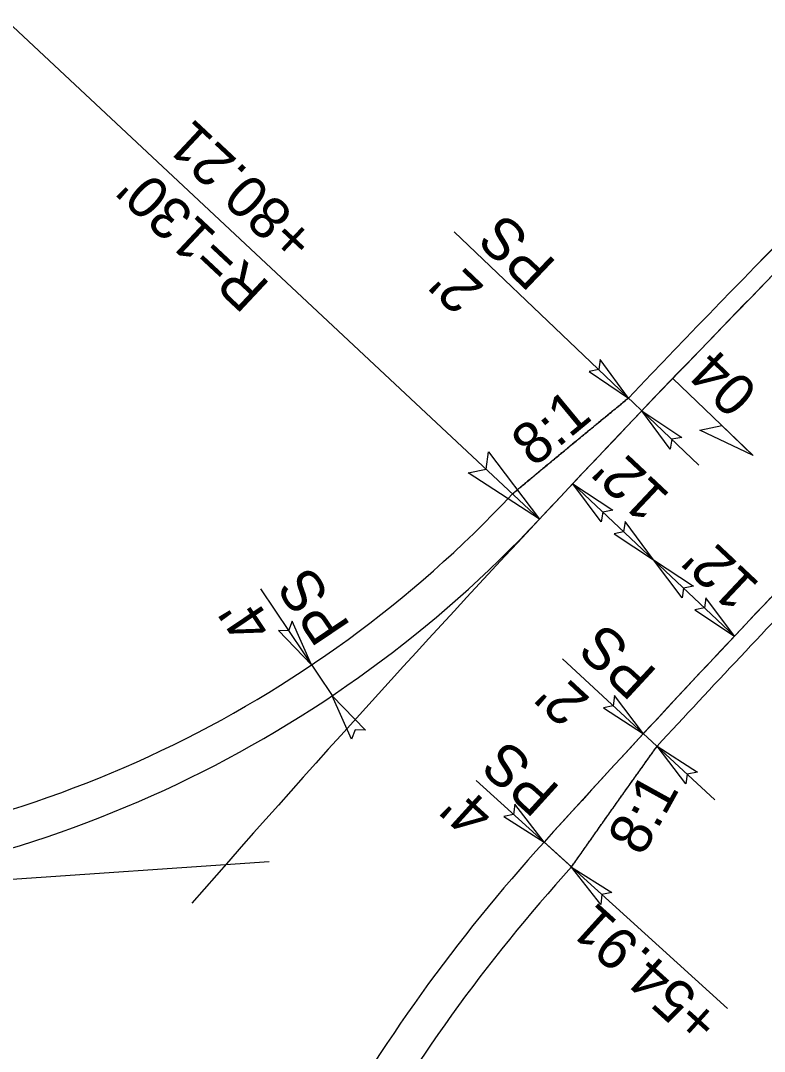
# Model space of a CAD drawing. Extents: x 1183930 to 1185370, y 573068 to 574871.
# Drawn here: x 1184757.1 to 1184837.4, y 574383.3 to 574494.7 of the extents above; entities that cross this region are included whole.
import ezdxf

# ---------------------------------------------------------------- set-up
doc = ezdxf.new("R2010")
doc.units = 0
for name, color, linetype in [('E_NCDOT_Terrain_Model_Contour_Minor', 7, 'Continuous'), ('E_NCDOT_Vertical_Profile_Ground_Line', 7, 'Continuous'), ('P_NCDOT_Horizontal_Alignment', 7, 'Continuous'), ('PC_COLUMN', 7, 'Continuous'), ('PC_OBJECT', 7, 'Continuous'), ('PC_PADFOOTING', 7, 'Continuous'), ('PC_SLAB', 7, 'Continuous')]:
    doc.layers.add(name, color=color, linetype=linetype)

msp = doc.modelspace()

# ---------------------------------------------------------------- linework, layer by layer
for points in [[(1184818.48, 574456.78), (1184822.74, 574453.91), (1184819.68, 574458.08), (1184819.53, 574456.98)], [(1184827.25, 574448.41), (1184824.19, 574452.53), (1184828.5, 574449.67), (1184827.41, 574449.47)], [(1184819.81, 574440.55), (1184816.72, 574444.65), (1184821.04, 574441.82), (1184819.96, 574441.6)], [(1184821.18, 574439.26), (1184825.46, 574436.43), (1184822.37, 574440.57), (1184822.22, 574439.47)], [(1184828.55, 574432.32), (1184825.46, 574436.43), (1184829.78, 574433.59), (1184828.7, 574433.38)], [(1184829.91, 574431.04), (1184834.2, 574428.2), (1184831.11, 574432.35), (1184830.96, 574431.25)], [(1184784.96, 574428.79), (1184788.51, 574425.08), (1184786.42, 574429.81), (1184786.03, 574428.77)], [(1184792.85, 574417.07), (1184790.74, 574421.76), (1184794.33, 574418.04), (1184793.22, 574418.07)], [(1184820.05, 574420.46), (1184824.36, 574417.66), (1184821.24, 574421.78), (1184821.1, 574420.68)], [(1184828.95, 574412.23), (1184825.83, 574416.3), (1184830.18, 574413.51), (1184829.09, 574413.29)], [(1184809.29, 574408.71), (1184813.63, 574405.95), (1184810.46, 574410.04), (1184810.34, 574408.94)], [(1184819.75, 574399.22), (1184816.59, 574403.26), (1184820.96, 574400.51), (1184819.88, 574400.28)]]:
    msp.add_lwpolyline(points, close=True)
at = {"layer": 'E_NCDOT_Terrain_Model_Contour_Minor'}
msp.add_line((1184718.19, 574529.63), (1184813.13, 574440.82), dxfattribs=at)
msp.add_lwpolyline([(1184807.61, 574448.1), (1184813.13, 574440.82), (1184805.42, 574445.83), (1184807.36, 574446.22)], close=True, dxfattribs=at)
at = {"layer": 'E_NCDOT_Vertical_Profile_Ground_Line'}
for centre, radius, start, end in [((1186063.32, 573271.23), 1714, 134.45507, 136.36856), ((1186063.32, 573271.23), 1714, 134.45507, 136.36856), ((1184718.19, 574529.63), 126, 273.9365, 316.9078), ((1184718.19, 574529.63), 126, 273.9365, 316.9078), ((1186063.32, 573271.23), 1686, 136.32379, 137.22125), ((1186063.32, 573271.23), 1686, 136.32379, 137.22125), ((1184950.59, 574281.59), 181, 137.7604, 163.7957), ((1184950.59, 574281.59), 181, 137.7604, 163.7957)]:
    msp.add_arc(centre, radius, start, end, dxfattribs=at)
for points in [[(1184810.21, 574443.55), (1184810.41, 574443.73), (1184810.83, 574444.07), (1184811.46, 574444.59), (1184812.08, 574445.12), (1184812.71, 574445.64), (1184813.33, 574446.16), (1184813.96, 574446.68), (1184814.58, 574447.19), (1184815.21, 574447.71), (1184815.84, 574448.23), (1184816.46, 574448.75), (1184817.09, 574449.27), (1184817.72, 574449.79), (1184818.34, 574450.3), (1184818.97, 574450.82), (1184819.6, 574451.34), (1184820.23, 574451.85), (1184820.86, 574452.37), (1184821.48, 574452.88), (1184822.11, 574453.4), (1184822.53, 574453.74), (1184822.74, 574453.91)], [(1184810.21, 574443.55), (1184810.41, 574443.73), (1184810.83, 574444.07), (1184811.46, 574444.59), (1184812.08, 574445.12), (1184812.71, 574445.64), (1184813.33, 574446.16), (1184813.96, 574446.68), (1184814.58, 574447.19), (1184815.21, 574447.71), (1184815.84, 574448.23), (1184816.46, 574448.75), (1184817.09, 574449.27), (1184817.72, 574449.79), (1184818.34, 574450.3), (1184818.97, 574450.82), (1184819.6, 574451.34), (1184820.23, 574451.85), (1184820.86, 574452.37), (1184821.48, 574452.88), (1184822.11, 574453.4), (1184822.53, 574453.74), (1184822.74, 574453.91)], [(1184816.59, 574403.26), (1184816.74, 574403.48), (1184817.05, 574403.92), (1184817.51, 574404.57), (1184817.97, 574405.22), (1184818.43, 574405.88), (1184818.89, 574406.53), (1184819.35, 574407.18), (1184819.81, 574407.84), (1184820.27, 574408.49), (1184820.73, 574409.14), (1184821.19, 574409.79), (1184821.66, 574410.45), (1184822.12, 574411.1), (1184822.58, 574411.75), (1184823.04, 574412.4), (1184823.51, 574413.05), (1184823.97, 574413.7), (1184824.44, 574414.35), (1184824.9, 574415), (1184825.37, 574415.65), (1184825.68, 574416.09), (1184825.83, 574416.3)], [(1184816.59, 574403.26), (1184816.74, 574403.48), (1184817.05, 574403.92), (1184817.51, 574404.57), (1184817.97, 574405.22), (1184818.43, 574405.88), (1184818.89, 574406.53), (1184819.35, 574407.18), (1184819.81, 574407.84), (1184820.27, 574408.49), (1184820.73, 574409.14), (1184821.19, 574409.79), (1184821.66, 574410.45), (1184822.12, 574411.1), (1184822.58, 574411.75), (1184823.04, 574412.4), (1184823.51, 574413.05), (1184823.97, 574413.7), (1184824.44, 574414.35), (1184824.9, 574415), (1184825.37, 574415.65), (1184825.68, 574416.09), (1184825.83, 574416.3)]]:
    msp.add_open_spline(points, degree=3, dxfattribs=at)
at = {"layer": 'P_NCDOT_Horizontal_Alignment'}
msp.add_line((1184592.27, 574390.66), (1184783.93, 574403.85), dxfattribs=at)
for centre, radius, start, end in [((1186063.32, 573271.23), 1712, 134.45454, 138.77988), ((1186063.32, 573271.23), 1712, 134.45454, 136.90785), ((1186063.32, 573271.23), 1712, 134.45454, 136.90785), ((1186063.32, 573271.23), 1688, 134.45454, 137.76045), ((1186063.32, 573271.23), 1688, 134.45454, 137.76045), ((1184718.19, 574529.63), 130, 273.9365, 316.9078), ((1184718.19, 574529.63), 130, 273.9365, 316.9078), ((1184950.59, 574281.59), 185, 137.7604, 163.7957)]:
    msp.add_arc(centre, radius, start, end, dxfattribs=at)
at = {"layer": 'PC_COLUMN'}
msp.add_lwpolyline([(1184836.15, 574447.73), (1184830.44, 574450.45), (1184832.82, 574450.94)], close=True, dxfattribs=at)
at = {"layer": 'PC_OBJECT'}
msp.add_lwpolyline([(1184810.21, 574443.55), (1184810.21, 574443.55)], dxfattribs=at)
for centre, radius, start, end in [((1186063.32, 573271.23), 1714, 134.45454, 136.36856), ((1186063.32, 573271.23), 1712, 134.45454, 136.90785), ((1184718.19, 574529.63), 126, 273.9365, 316.9078), ((1184718.19, 574529.63), 130, 273.9365, 316.9078), ((1186063.32, 573271.23), 1686, 136.32379, 137.22125), ((1186063.32, 573271.23), 1688, 136.53929, 137.76045), ((1184950.59, 574281.59), 185, 137.7604, 163.7957), ((1184950.59, 574281.59), 181, 137.7604, 163.7957)]:
    msp.add_arc(centre, radius, start, end, dxfattribs=at)
for points in [[(1184822.74, 574453.91), (1184822.4, 574453.64), (1184822.23, 574453.5), (1184822.06, 574453.36), (1184821.89, 574453.22), (1184821.72, 574453.08), (1184821.55, 574452.94), (1184821.38, 574452.8), (1184821.21, 574452.66), (1184821.04, 574452.52), (1184820.87, 574452.38), (1184820.7, 574452.24), (1184820.53, 574452.1), (1184820.36, 574451.96), (1184820.19, 574451.82), (1184820.02, 574451.69), (1184819.85, 574451.55), (1184819.69, 574451.41), (1184819.52, 574451.27), (1184819.35, 574451.13), (1184819.18, 574450.99), (1184819.01, 574450.85), (1184818.84, 574450.71), (1184818.67, 574450.57), (1184818.55, 574450.47)], [(1184818.55, 574450.47), (1184818.5, 574450.43), (1184818.33, 574450.29), (1184818.16, 574450.15), (1184817.99, 574450.01), (1184817.82, 574449.87), (1184817.65, 574449.73), (1184817.48, 574449.59), (1184817.31, 574449.45), (1184817.14, 574449.31), (1184816.97, 574449.17), (1184816.8, 574449.03), (1184816.63, 574448.89), (1184816.46, 574448.75), (1184816.29, 574448.61), (1184816.12, 574448.47), (1184815.96, 574448.33), (1184815.79, 574448.19), (1184815.62, 574448.05), (1184815.45, 574447.91), (1184815.28, 574447.77), (1184815.11, 574447.63), (1184814.94, 574447.49), (1184814.77, 574447.35), (1184814.6, 574447.21), (1184814.43, 574447.07), (1184814.37, 574447.02)], [(1184814.37, 574447.02), (1184814.26, 574446.93), (1184814.09, 574446.79), (1184813.92, 574446.65), (1184813.75, 574446.51), (1184813.59, 574446.37), (1184813.42, 574446.23), (1184813.25, 574446.09), (1184813.08, 574445.94), (1184812.91, 574445.8), (1184812.74, 574445.66), (1184812.57, 574445.52), (1184812.4, 574445.38), (1184812.23, 574445.24), (1184812.06, 574445.1), (1184811.89, 574444.96), (1184811.73, 574444.82), (1184811.56, 574444.68), (1184811.39, 574444.54), (1184811.22, 574444.4), (1184811.05, 574444.26), (1184810.88, 574444.12), (1184810.71, 574443.98), (1184810.54, 574443.83), (1184810.37, 574443.69), (1184810.21, 574443.55)]]:
    msp.add_spline(points, degree=3, dxfattribs=at)
for points in [[(1184825.67, 574416.08), (1184825.72, 574416.15), (1184825.78, 574416.23), (1184825.83, 574416.3)], [(1184824.9, 574415), (1184824.92, 574415.03), (1184824.93, 574415.05), (1184824.95, 574415.07)], [(1184824.95, 574415.07), (1184824.95, 574415.08), (1184824.96, 574415.09), (1184824.97, 574415.1)], [(1184824.97, 574415.1), (1184824.99, 574415.13), (1184825.02, 574415.17), (1184825.04, 574415.2)], [(1184825.04, 574415.2), (1184825.07, 574415.24), (1184825.1, 574415.29), (1184825.13, 574415.33)], [(1184825.13, 574415.33), (1184825.17, 574415.38), (1184825.21, 574415.44), (1184825.25, 574415.49)], [(1184825.25, 574415.49), (1184825.26, 574415.5), (1184825.26, 574415.51), (1184825.27, 574415.52)], [(1184825.27, 574415.52), (1184825.3, 574415.57), (1184825.33, 574415.61), (1184825.37, 574415.65)], [(1184825.37, 574415.65), (1184825.37, 574415.67), (1184825.38, 574415.68), (1184825.39, 574415.69)], [(1184825.39, 574415.69), (1184825.4, 574415.7), (1184825.4, 574415.71), (1184825.41, 574415.72)], [(1184825.41, 574415.72), (1184825.45, 574415.77), (1184825.49, 574415.83), (1184825.53, 574415.88)], [(1184825.53, 574415.88), (1184825.54, 574415.9), (1184825.56, 574415.93), (1184825.57, 574415.95)], [(1184825.57, 574415.95), (1184825.58, 574415.96), (1184825.59, 574415.97), (1184825.6, 574415.98)], [(1184825.6, 574415.98), (1184825.61, 574415.99), (1184825.61, 574416), (1184825.62, 574416.01)], [(1184825.62, 574416.01), (1184825.63, 574416.02), (1184825.64, 574416.03), (1184825.64, 574416.04)], [(1184825.64, 574416.04), (1184825.65, 574416.06), (1184825.66, 574416.07), (1184825.67, 574416.08)], [(1184824.09, 574413.87), (1184824.1, 574413.89), (1184824.12, 574413.91), (1184824.13, 574413.93)], [(1184824.13, 574413.93), (1184824.15, 574413.95), (1184824.17, 574413.97), (1184824.18, 574414)], [(1184824.18, 574414), (1184824.2, 574414.03), (1184824.23, 574414.06), (1184824.25, 574414.09)], [(1184824.25, 574414.09), (1184824.26, 574414.1), (1184824.27, 574414.11), (1184824.27, 574414.13)], [(1184824.27, 574414.13), (1184824.29, 574414.15), (1184824.3, 574414.17), (1184824.32, 574414.19)], [(1184824.32, 574414.19), (1184824.34, 574414.22), (1184824.37, 574414.26), (1184824.39, 574414.29)], [(1184824.39, 574414.29), (1184824.41, 574414.31), (1184824.42, 574414.33), (1184824.44, 574414.35)], [(1184824.44, 574414.35), (1184824.47, 574414.4), (1184824.5, 574414.44), (1184824.53, 574414.48)], [(1184824.53, 574414.48), (1184824.54, 574414.49), (1184824.54, 574414.51), (1184824.55, 574414.52)], [(1184824.55, 574414.52), (1184824.57, 574414.54), (1184824.58, 574414.56), (1184824.6, 574414.58)], [(1184824.6, 574414.58), (1184824.63, 574414.62), (1184824.66, 574414.67), (1184824.69, 574414.71)], [(1184824.69, 574414.71), (1184824.72, 574414.75), (1184824.75, 574414.8), (1184824.78, 574414.84)], [(1184824.78, 574414.84), (1184824.82, 574414.9), (1184824.86, 574414.95), (1184824.9, 574415)], [(1184823.25, 574412.69), (1184823.29, 574412.75), (1184823.33, 574412.8), (1184823.37, 574412.86)], [(1184823.37, 574412.86), (1184823.39, 574412.89), (1184823.42, 574412.92), (1184823.44, 574412.95)], [(1184823.44, 574412.95), (1184823.46, 574412.99), (1184823.48, 574413.02), (1184823.51, 574413.05)], [(1184823.51, 574413.05), (1184823.55, 574413.12), (1184823.6, 574413.18), (1184823.65, 574413.25)], [(1184823.65, 574413.25), (1184823.65, 574413.26), (1184823.66, 574413.27), (1184823.67, 574413.28)], [(1184823.67, 574413.28), (1184823.74, 574413.38), (1184823.81, 574413.47), (1184823.88, 574413.57)], [(1184823.88, 574413.57), (1184823.89, 574413.59), (1184823.91, 574413.62), (1184823.93, 574413.64)], [(1184823.93, 574413.64), (1184823.94, 574413.66), (1184823.96, 574413.68), (1184823.97, 574413.7)], [(1184823.97, 574413.7), (1184824, 574413.75), (1184824.03, 574413.79), (1184824.06, 574413.83)], [(1184824.06, 574413.83), (1184824.07, 574413.84), (1184824.08, 574413.85), (1184824.09, 574413.87)], [(1184822.53, 574411.68), (1184822.55, 574411.71), (1184822.57, 574411.73), (1184822.58, 574411.75)], [(1184822.58, 574411.75), (1184822.59, 574411.76), (1184822.6, 574411.77), (1184822.6, 574411.78)], [(1184822.6, 574411.78), (1184822.64, 574411.82), (1184822.67, 574411.87), (1184822.7, 574411.91)], [(1184822.7, 574411.91), (1184822.7, 574411.92), (1184822.71, 574411.93), (1184822.72, 574411.94)], [(1184822.72, 574411.94), (1184822.74, 574411.97), (1184822.75, 574411.99), (1184822.77, 574412.01)], [(1184822.77, 574412.01), (1184822.77, 574412.02), (1184822.78, 574412.03), (1184822.79, 574412.04)], [(1184822.79, 574412.04), (1184822.8, 574412.05), (1184822.81, 574412.06), (1184822.81, 574412.07)], [(1184822.81, 574412.07), (1184822.83, 574412.1), (1184822.84, 574412.12), (1184822.86, 574412.14)], [(1184822.86, 574412.14), (1184822.87, 574412.15), (1184822.87, 574412.16), (1184822.88, 574412.17)], [(1184822.88, 574412.17), (1184822.92, 574412.23), (1184822.96, 574412.28), (1184823, 574412.34)], [(1184823, 574412.34), (1184823.01, 574412.36), (1184823.03, 574412.38), (1184823.04, 574412.4)], [(1184823.04, 574412.4), (1184823.05, 574412.41), (1184823.06, 574412.42), (1184823.07, 574412.43)], [(1184823.07, 574412.43), (1184823.1, 574412.48), (1184823.13, 574412.52), (1184823.16, 574412.56)], [(1184823.16, 574412.56), (1184823.19, 574412.61), (1184823.22, 574412.65), (1184823.25, 574412.69)], [(1184821.66, 574410.45), (1184821.73, 574410.54), (1184821.79, 574410.64), (1184821.86, 574410.74)], [(1184821.86, 574410.74), (1184821.88, 574410.76), (1184821.89, 574410.78), (1184821.91, 574410.8)], [(1184821.91, 574410.8), (1184821.94, 574410.85), (1184821.97, 574410.89), (1184822, 574410.93)], [(1184822, 574410.93), (1184822.04, 574410.99), (1184822.08, 574411.04), (1184822.12, 574411.1)], [(1184822.12, 574411.1), (1184822.13, 574411.11), (1184822.13, 574411.12), (1184822.14, 574411.13)], [(1184822.14, 574411.13), (1184822.18, 574411.18), (1184822.22, 574411.24), (1184822.26, 574411.29)], [(1184822.26, 574411.29), (1184822.33, 574411.4), (1184822.41, 574411.51), (1184822.49, 574411.62)], [(1184822.49, 574411.62), (1184822.5, 574411.63), (1184822.5, 574411.64), (1184822.51, 574411.65)], [(1184822.51, 574411.65), (1184822.52, 574411.66), (1184822.53, 574411.67), (1184822.53, 574411.68)], [(1184820.92, 574409.4), (1184820.95, 574409.46), (1184820.99, 574409.51), (1184821.03, 574409.57)], [(1184821.03, 574409.57), (1184821.09, 574409.64), (1184821.14, 574409.72), (1184821.19, 574409.79)], [(1184821.19, 574409.79), (1184821.21, 574409.82), (1184821.22, 574409.84), (1184821.24, 574409.86)], [(1184821.24, 574409.86), (1184821.26, 574409.89), (1184821.29, 574409.92), (1184821.31, 574409.96)], [(1184821.31, 574409.96), (1184821.32, 574409.97), (1184821.32, 574409.98), (1184821.33, 574409.99)], [(1184821.33, 574409.99), (1184821.34, 574410), (1184821.35, 574410.01), (1184821.36, 574410.02)], [(1184821.36, 574410.02), (1184821.36, 574410.03), (1184821.37, 574410.04), (1184821.38, 574410.05)], [(1184821.38, 574410.05), (1184821.39, 574410.07), (1184821.39, 574410.08), (1184821.4, 574410.09)], [(1184821.4, 574410.09), (1184821.41, 574410.1), (1184821.42, 574410.11), (1184821.42, 574410.12)], [(1184821.42, 574410.12), (1184821.47, 574410.18), (1184821.52, 574410.25), (1184821.56, 574410.32)], [(1184821.56, 574410.32), (1184821.57, 574410.33), (1184821.58, 574410.34), (1184821.59, 574410.35)], [(1184821.59, 574410.35), (1184821.59, 574410.36), (1184821.6, 574410.37), (1184821.61, 574410.38)], [(1184821.61, 574410.38), (1184821.62, 574410.39), (1184821.62, 574410.4), (1184821.63, 574410.41)], [(1184821.63, 574410.41), (1184821.64, 574410.42), (1184821.65, 574410.43), (1184821.66, 574410.45)], [(1184819.88, 574407.93), (1184820.01, 574408.12), (1184820.14, 574408.3), (1184820.27, 574408.49)], [(1184820.27, 574408.49), (1184820.29, 574408.52), (1184820.32, 574408.55), (1184820.34, 574408.59)], [(1184820.34, 574408.59), (1184820.4, 574408.67), (1184820.46, 574408.76), (1184820.52, 574408.85)], [(1184820.52, 574408.85), (1184820.55, 574408.89), (1184820.59, 574408.93), (1184820.62, 574408.98)], [(1184820.62, 574408.98), (1184820.63, 574409), (1184820.65, 574409.02), (1184820.66, 574409.04)], [(1184820.66, 574409.04), (1184820.68, 574409.07), (1184820.69, 574409.09), (1184820.71, 574409.11)], [(1184820.71, 574409.11), (1184820.72, 574409.12), (1184820.72, 574409.13), (1184820.73, 574409.14)], [(1184820.73, 574409.14), (1184820.75, 574409.17), (1184820.78, 574409.21), (1184820.8, 574409.24)], [(1184820.8, 574409.24), (1184820.81, 574409.25), (1184820.82, 574409.26), (1184820.82, 574409.27)], [(1184820.82, 574409.27), (1184820.85, 574409.32), (1184820.89, 574409.36), (1184820.92, 574409.4)], [(1184819.37, 574407.22), (1184819.5, 574407.4), (1184819.63, 574407.59), (1184819.76, 574407.77)], [(1184819.76, 574407.77), (1184819.77, 574407.78), (1184819.78, 574407.79), (1184819.79, 574407.8)], [(1184819.79, 574407.8), (1184819.79, 574407.81), (1184819.8, 574407.83), (1184819.81, 574407.84)], [(1184819.81, 574407.84), (1184819.82, 574407.85), (1184819.82, 574407.86), (1184819.83, 574407.87)], [(1184819.83, 574407.87), (1184819.85, 574407.89), (1184819.86, 574407.91), (1184819.88, 574407.93)], [(1184818.57, 574406.07), (1184818.59, 574406.11), (1184818.61, 574406.14), (1184818.63, 574406.17)], [(1184818.63, 574406.17), (1184818.64, 574406.18), (1184818.65, 574406.19), (1184818.66, 574406.2)], [(1184818.66, 574406.2), (1184818.68, 574406.24), (1184818.7, 574406.27), (1184818.73, 574406.3)], [(1184818.73, 574406.3), (1184818.73, 574406.31), (1184818.74, 574406.32), (1184818.75, 574406.34)], [(1184818.75, 574406.34), (1184818.77, 574406.37), (1184818.8, 574406.4), (1184818.82, 574406.43)], [(1184818.82, 574406.43), (1184818.84, 574406.47), (1184818.86, 574406.5), (1184818.89, 574406.53)], [(1184818.89, 574406.53), (1184818.92, 574406.57), (1184818.95, 574406.62), (1184818.98, 574406.66)], [(1184818.98, 574406.66), (1184818.99, 574406.67), (1184819, 574406.68), (1184819, 574406.69)], [(1184819, 574406.69), (1184819.02, 574406.72), (1184819.03, 574406.74), (1184819.05, 574406.76)], [(1184819.05, 574406.76), (1184819.06, 574406.77), (1184819.06, 574406.78), (1184819.07, 574406.79)], [(1184819.07, 574406.79), (1184819.09, 574406.81), (1184819.1, 574406.84), (1184819.12, 574406.86)], [(1184819.12, 574406.86), (1184819.15, 574406.9), (1184819.18, 574406.94), (1184819.21, 574406.99)], [(1184819.21, 574406.99), (1184819.22, 574407), (1184819.23, 574407.01), (1184819.23, 574407.02)], [(1184819.23, 574407.02), (1184819.25, 574407.04), (1184819.26, 574407.06), (1184819.28, 574407.09)], [(1184819.28, 574407.09), (1184819.3, 574407.12), (1184819.33, 574407.15), (1184819.35, 574407.18)], [(1184819.35, 574407.18), (1184819.36, 574407.19), (1184819.36, 574407.21), (1184819.37, 574407.22)], [(1184817.78, 574404.96), (1184817.85, 574405.05), (1184817.91, 574405.14), (1184817.97, 574405.22)], [(1184817.97, 574405.22), (1184817.99, 574405.26), (1184818.01, 574405.29), (1184818.04, 574405.32)], [(1184818.04, 574405.32), (1184818.08, 574405.39), (1184818.13, 574405.45), (1184818.17, 574405.52)], [(1184818.17, 574405.52), (1184818.2, 574405.55), (1184818.22, 574405.58), (1184818.24, 574405.62)], [(1184818.24, 574405.62), (1184818.26, 574405.64), (1184818.27, 574405.66), (1184818.29, 574405.68)], [(1184818.29, 574405.68), (1184818.3, 574405.69), (1184818.3, 574405.7), (1184818.31, 574405.71)], [(1184818.31, 574405.71), (1184818.35, 574405.77), (1184818.39, 574405.82), (1184818.43, 574405.88)], [(1184818.43, 574405.88), (1184818.44, 574405.89), (1184818.44, 574405.9), (1184818.45, 574405.91)], [(1184818.45, 574405.91), (1184818.49, 574405.97), (1184818.53, 574406.02), (1184818.57, 574406.07)], [(1184817.03, 574403.89), (1184817.03, 574403.9), (1184817.04, 574403.91), (1184817.05, 574403.92)], [(1184817.05, 574403.92), (1184817.06, 574403.93), (1184817.06, 574403.94), (1184817.07, 574403.95)], [(1184817.07, 574403.95), (1184817.1, 574403.98), (1184817.12, 574404.02), (1184817.14, 574404.05)], [(1184817.14, 574404.05), (1184817.15, 574404.06), (1184817.16, 574404.07), (1184817.16, 574404.08)], [(1184817.16, 574404.08), (1184817.19, 574404.11), (1184817.21, 574404.15), (1184817.23, 574404.18)], [(1184817.23, 574404.18), (1184817.29, 574404.26), (1184817.34, 574404.33), (1184817.39, 574404.41)], [(1184817.39, 574404.41), (1184817.43, 574404.46), (1184817.47, 574404.52), (1184817.51, 574404.57)], [(1184817.51, 574404.57), (1184817.53, 574404.6), (1184817.55, 574404.64), (1184817.58, 574404.67)], [(1184817.58, 574404.67), (1184817.62, 574404.73), (1184817.67, 574404.8), (1184817.71, 574404.87)], [(1184817.71, 574404.87), (1184817.74, 574404.9), (1184817.76, 574404.93), (1184817.78, 574404.96)], [(1184816.59, 574403.26), (1184816.6, 574403.28), (1184816.61, 574403.29), (1184816.61, 574403.3)], [(1184816.61, 574403.3), (1184816.69, 574403.41), (1184816.77, 574403.51), (1184816.84, 574403.62)], [(1184816.84, 574403.62), (1184816.85, 574403.63), (1184816.86, 574403.65), (1184816.87, 574403.66)], [(1184816.87, 574403.66), (1184816.87, 574403.67), (1184816.88, 574403.68), (1184816.89, 574403.69)], [(1184816.89, 574403.69), (1184816.93, 574403.75), (1184816.98, 574403.82), (1184817.03, 574403.89)]]:
    msp.add_open_spline(points, degree=2, dxfattribs=at)
at = {"layer": 'PC_PADFOOTING'}
for p, q in [((1184803.93, 574471.85), (1184830.34, 574446.67)), ((1184816.72, 574444.65), (1184834.19, 574428.21)), ((1184782.99, 574433.29), (1184790.74, 574421.77)), ((1184815.63, 574425.75), (1184832.07, 574410.53)), ((1184806.3, 574412.61), (1184816.58, 574403.27)), ((1184813.63, 574405.95), (1184833.45, 574387.96))]:
    msp.add_line(p, q, dxfattribs=at)
at = {"layer": 'PC_SLAB'}
msp.add_line((1184827.52, 574456.02), (1184836.19, 574447.72), dxfattribs=at)

# ---------------------------------------------------------------- texts
at = {"layer": 'E_NCDOT_Terrain_Model_Contour_Minor'}
for s, p in [('+80.21', (1184789.29, 574471.46)), ("R=130'", (1184784.19, 574466.17))]:
    msp.add_text(s, height=4.5, rotation=136.9078, dxfattribs=at).set_placement(p)
at = {"layer": 'PC_PADFOOTING'}
for s, rotation, p in [('PS', 136.3686, (1184815.11, 574468.5)), ("2'", 136.3686, (1184807.32, 574465.88)), ('8:1', 39.5749, (1184812.52, 574446.34)), ("12'", 136.732, (1184827.38, 574443.4)), ("12'", 136.732, (1184837.07, 574433.79)), ('PS', 123.9236, (1184792.81, 574429.3)), ("4'", 123.9236, (1184784.53, 574429.29)), ('PS', 137.2213, (1184826, 574424.33)), ("2'", 137.2213, (1184818.74, 574421.4)), ('PS', 137.7604, (1184815.52, 574411.75)), ('8:1', 61.1127, (1184824.23, 574404.29)), ("4'", 137.7604, (1184808.49, 574409.33)), ('+54.91', 137.8598, (1184833.02, 574387.06))]:
    msp.add_text(s, height=4.5, rotation=rotation, dxfattribs=at).set_placement(p)
at = {"layer": 'PC_SLAB'}
msp.add_text('04', height=4.5, rotation=136.0663, dxfattribs=at).set_placement((1184836.93, 574454.78))

doc.saveas('drawing.dxf')
